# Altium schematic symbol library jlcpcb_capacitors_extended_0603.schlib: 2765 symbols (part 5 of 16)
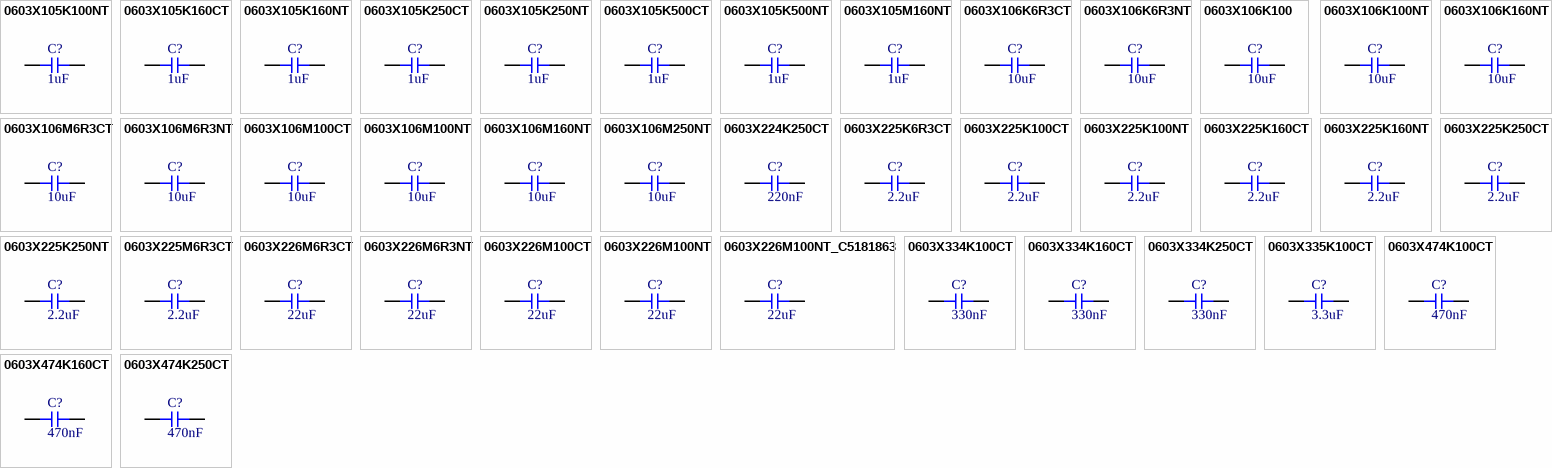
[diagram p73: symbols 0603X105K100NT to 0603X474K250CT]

## 0603X474K250CT
designator C?  Capacitance: 470nF  (hidden comment: *)
Capacitor, Ceramic (MLCC), 470nF, ±10%, 25V, X5R, ±10%, SMD 0603; Manufacturer: Walsin Tech Corp; Manufacturer Part Number: 0603X474K250CT
footprint CAP-0603 (0603 (1608M) Capacitor)
pins: 1, 2

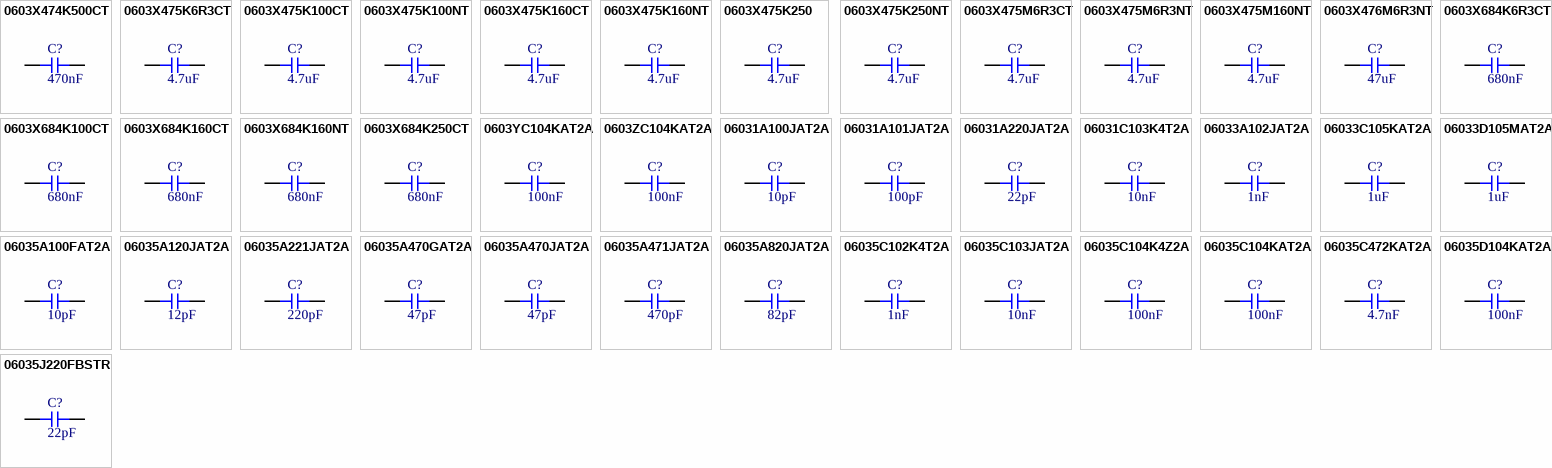
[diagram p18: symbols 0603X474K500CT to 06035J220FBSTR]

## 0603X474K500CT
designator C?  Capacitance: 470nF  (hidden comment: *)
Capacitor, Ceramic (MLCC), 470nF, ±10%, 50V, X5R, ±10%, SMD 0603; Manufacturer: Walsin Tech Corp; Manufacturer Part Number: 0603X474K500CT
footprint CAP-0603 (0603 (1608M) Capacitor)
pins: 1, 2

## 0603X475K6R3CT
designator C?  Capacitance: 4.7uF  (hidden comment: *)
Capacitor, Ceramic (MLCC), 4.7uF, ±10%, 6.3V, X5R, ±10%, SMD 0603; Manufacturer: Walsin Tech Corp; Manufacturer Part Number: 0603X475K6R3CT
footprint CAP-0603 (0603 (1608M) Capacitor)
pins: 1, 2

## 0603X475K100CT
designator C?  Capacitance: 4.7uF  (hidden comment: *)
Capacitor, Ceramic (MLCC), 4.7uF, ±10%, 10V, X5R, ±10%, SMD 0603; Manufacturer: Walsin Tech Corp; Manufacturer Part Number: 0603X475K100CT
footprint CAP-0603 (0603 (1608M) Capacitor)
pins: 1, 2

## 0603X475K100NT
designator C?  Capacitance: 4.7uF  (hidden comment: *)
Capacitor, Ceramic (MLCC), 4.7uF, ±10%, 10V, X5R, ±10%, SMD 0603; Manufacturer: FH(Guangdong Fenghua Advanced Tech); Manufacturer Part Number: 0603X475K100NT
footprint CAP-0603 (0603 (1608M) Capacitor)
pins: 1, 2

## 0603X475K160CT
designator C?  Capacitance: 4.7uF  (hidden comment: *)
Capacitor, Ceramic (MLCC), 4.7uF, ±10%, 16V, X5R, ±10%, SMD 0603; Manufacturer: Walsin Tech Corp; Manufacturer Part Number: 0603X475K160CT
footprint CAP-0603 (0603 (1608M) Capacitor)
pins: 1, 2

## 0603X475K160NT
designator C?  Capacitance: 4.7uF  (hidden comment: *)
Capacitor, Ceramic (MLCC), 4.7uF, ±10%, 16V, X5R, ±10%, SMD 0603; Manufacturer: FH(Guangdong Fenghua Advanced Tech); Manufacturer Part Number: 0603X475K160NT
footprint CAP-0603 (0603 (1608M) Capacitor)
pins: 1, 2

## 0603X475K250
designator C?  Capacitance: 4.7uF  (hidden comment: *)
Capacitor, Ceramic (MLCC), 4.7uF, ±10%, 25V, X5R, ±10%, SMD 0603; Manufacturer: Walsin Tech Corp; Manufacturer Part Number: 0603X475K250
footprint CAP-0603 (0603 (1608M) Capacitor)
pins: 1, 2

## 0603X475K250NT
designator C?  Capacitance: 4.7uF  (hidden comment: *)
Capacitor, Ceramic (MLCC), 4.7uF, ±10%, 25V, X5R, ±10%, SMD 0603; Manufacturer: FH(Guangdong Fenghua Advanced Tech); Manufacturer Part Number: 0603X475K250NT
footprint CAP-0603 (0603 (1608M) Capacitor)
pins: 1, 2

## 0603X475M6R3CT
designator C?  Capacitance: 4.7uF  (hidden comment: *)
Capacitor, Ceramic (MLCC), 4.7uF, ±20%, 6.3V, X5R, ±20%, SMD 0603; Manufacturer: Walsin Tech Corp; Manufacturer Part Number: 0603X475M6R3CT
footprint CAP-0603 (0603 (1608M) Capacitor)
pins: 1, 2

## 0603X475M6R3NT
designator C?  Capacitance: 4.7uF  (hidden comment: *)
Capacitor, Ceramic (MLCC), 4.7uF, ±20%, 6.3V, X5R, ±20%, SMD 0603; Manufacturer: FH(Guangdong Fenghua Advanced Tech); Manufacturer Part Number: 0603X475M6R3NT
footprint CAP-0603 (0603 (1608M) Capacitor)
pins: 1, 2

## 0603X475M160NT
designator C?  Capacitance: 4.7uF  (hidden comment: *)
Capacitor, Ceramic (MLCC), 4.7uF, ±20%, 16V, X5R, ±20%, SMD 0603; Manufacturer: FH(Guangdong Fenghua Advanced Tech); Manufacturer Part Number: 0603X475M160NT
footprint CAP-0603 (0603 (1608M) Capacitor)
pins: 1, 2

## 0603X476M6R3NT
designator C?  Capacitance: 47uF  (hidden comment: *)
Capacitor, Ceramic (MLCC), 47uF, ±20%, 6.3V, X5R, ±20%, SMD 0603; Manufacturer: FH(Guangdong Fenghua Advanced Tech); Manufacturer Part Number: 0603X476M6R3NT
footprint CAP-0603 (0603 (1608M) Capacitor)
pins: 1, 2

## 0603X684K6R3CT
designator C?  Capacitance: 680nF  (hidden comment: *)
Capacitor, Ceramic (MLCC), 680nF, ±10%, 6.3V, X5R, ±10%, SMD 0603; Manufacturer: Walsin Tech Corp; Manufacturer Part Number: 0603X684K6R3CT
footprint CAP-0603 (0603 (1608M) Capacitor)
pins: 1, 2

## 0603X684K100CT
designator C?  Capacitance: 680nF  (hidden comment: *)
Capacitor, Ceramic (MLCC), 680nF, ±10%, 10V, X5R, ±10%, SMD 0603; Manufacturer: Walsin Tech Corp; Manufacturer Part Number: 0603X684K100CT
footprint CAP-0603 (0603 (1608M) Capacitor)
pins: 1, 2

## 0603X684K160CT
designator C?  Capacitance: 680nF  (hidden comment: *)
Capacitor, Ceramic (MLCC), 680nF, ±10%, 16V, X5R, ±10%, SMD 0603; Manufacturer: Walsin Tech Corp; Manufacturer Part Number: 0603X684K160CT
footprint CAP-0603 (0603 (1608M) Capacitor)
pins: 1, 2

## 0603X684K160NT
designator C?  Capacitance: 680nF  (hidden comment: *)
Capacitor, Ceramic (MLCC), 680nF, ±10%, 16V, ±10%, SMD 0603; Manufacturer: FH(Guangdong Fenghua Advanced Tech); Manufacturer Part Number: 0603X684K160NT
footprint CAP-0603 (0603 (1608M) Capacitor)
pins: 1, 2

## 0603X684K250CT
designator C?  Capacitance: 680nF  (hidden comment: *)
Capacitor, Ceramic (MLCC), 680nF, ±10%, 25V, X5R, ±10%, SMD 0603; Manufacturer: Walsin Tech Corp; Manufacturer Part Number: 0603X684K250CT
footprint CAP-0603 (0603 (1608M) Capacitor)
pins: 1, 2

## 0603YC104KAT2A
designator C?  Capacitance: 100nF  (hidden comment: *)
Capacitor, Ceramic (MLCC), 100nF, ±10%, 16V, X7R, ±10%, SMD 0603; Manufacturer: AVX; Manufacturer Part Number: 0603YC104KAT2A
footprint CAP-0603 (0603 (1608M) Capacitor)
pins: 1, 2

## 0603ZC104KAT2A
designator C?  Capacitance: 100nF  (hidden comment: *)
Capacitor, Ceramic (MLCC), 100nF, ±10%, 10V, X7R, ±10%, SMD 0603; Manufacturer: AVX; Manufacturer Part Number: 0603ZC104KAT2A
footprint CAP-0603 (0603 (1608M) Capacitor)
pins: 1, 2

## 06031A100JAT2A
designator C?  Capacitance: 10pF  (hidden comment: *)
Capacitor, Ceramic (MLCC), 10pF, ±5%, 100V, C0G, ±5%, SMD 0603; Manufacturer: AVX; Manufacturer Part Number: 06031A100JAT2A
footprint CAP-0603 (0603 (1608M) Capacitor)
pins: 1, 2

## 06031A101JAT2A
designator C?  Capacitance: 100pF  (hidden comment: *)
Capacitor, Ceramic (MLCC), 100pF, ±5%, 100V, C0G, ±5%, SMD 0603; Manufacturer: AVX; Manufacturer Part Number: 06031A101JAT2A
footprint CAP-0603 (0603 (1608M) Capacitor)
pins: 1, 2

## 06031A220JAT2A
designator C?  Capacitance: 22pF  (hidden comment: *)
Capacitor, Ceramic (MLCC), 22pF, ±5%, 100V, C0G, ±5%, SMD 0603; Manufacturer: AVX; Manufacturer Part Number: 06031A220JAT2A
footprint CAP-0603 (0603 (1608M) Capacitor)
pins: 1, 2

## 06031C103K4T2A
designator C?  Capacitance: 10nF  (hidden comment: *)
Capacitor, Ceramic (MLCC), 10nF, ±10%, 100V, X7R, ±10%, SMD 0603; Manufacturer: AVX; Manufacturer Part Number: 06031C103K4T2A
footprint CAP-0603 (0603 (1608M) Capacitor)
pins: 1, 2

## 06033A102JAT2A
designator C?  Capacitance: 1nF  (hidden comment: *)
Capacitor, Ceramic (MLCC), 1nF, ±5%, 25V, C0G, ±5%, SMD 0603; Manufacturer: AVX; Manufacturer Part Number: 06033A102JAT2A
footprint CAP-0603 (0603 (1608M) Capacitor)
pins: 1, 2

## 06033C105KAT2A
designator C?  Capacitance: 1uF  (hidden comment: *)
Capacitor, Ceramic (MLCC), 1uF, ±10%, 25V, X7R, ±10%, SMD 0603; Manufacturer: AVX; Manufacturer Part Number: 06033C105KAT2A
footprint CAP-0603 (0603 (1608M) Capacitor)
pins: 1, 2

## 06033D105MAT2A
designator C?  Capacitance: 1uF  (hidden comment: *)
Capacitor, Ceramic (MLCC), 1uF, ±20%, 25V, X5R, ±20%, SMD 0603; Manufacturer: AVX; Manufacturer Part Number: 06033D105MAT2A
footprint CAP-0603 (0603 (1608M) Capacitor)
pins: 1, 2

## 06035A100FAT2A
designator C?  Capacitance: 10pF  (hidden comment: *)
Capacitor, Ceramic (MLCC), 10pF, ±1%, 50V, C0G, ±1%, SMD 0603; Manufacturer: AVX; Manufacturer Part Number: 06035A100FAT2A
footprint CAP-0603 (0603 (1608M) Capacitor)
pins: 1, 2

## 06035A120JAT2A
designator C?  Capacitance: 12pF  (hidden comment: *)
Capacitor, Ceramic (MLCC), 12pF, ±5%, 50V, C0G, ±5%, SMD 0603; Manufacturer: AVX; Manufacturer Part Number: 06035A120JAT2A
footprint CAP-0603 (0603 (1608M) Capacitor)
pins: 1, 2

## 06035A221JAT2A
designator C?  Capacitance: 220pF  (hidden comment: *)
Capacitor, Ceramic (MLCC), 220pF, ±5%, 50V, C0G, ±5%, SMD 0603; Manufacturer: AVX; Manufacturer Part Number: 06035A221JAT2A
footprint CAP-0603 (0603 (1608M) Capacitor)
pins: 1, 2

## 06035A470GAT2A
designator C?  Capacitance: 47pF  (hidden comment: *)
Capacitor, Ceramic (MLCC), 47pF, ±2%, 50V, C0G, ±2%, SMD 0603; Manufacturer: AVX; Manufacturer Part Number: 06035A470GAT2A
footprint CAP-0603 (0603 (1608M) Capacitor)
pins: 1, 2

## 06035A470JAT2A
designator C?  Capacitance: 47pF  (hidden comment: *)
Capacitor, Ceramic (MLCC), 47pF, ±5%, 50V, C0G, ±5%, SMD 0603; Manufacturer: AVX; Manufacturer Part Number: 06035A470JAT2A
footprint CAP-0603 (0603 (1608M) Capacitor)
pins: 1, 2

## 06035A471JAT2A
designator C?  Capacitance: 470pF  (hidden comment: *)
Capacitor, Ceramic (MLCC), 470pF, ±5%, 50V, C0G, ±5%, SMD 0603; Manufacturer: AVX; Manufacturer Part Number: 06035A471JAT2A
footprint CAP-0603 (0603 (1608M) Capacitor)
pins: 1, 2

## 06035A820JAT2A
designator C?  Capacitance: 82pF  (hidden comment: *)
Capacitor, Ceramic (MLCC), 82pF, ±5%, 50V, C0G, ±5%, SMD 0603; Manufacturer: AVX; Manufacturer Part Number: 06035A820JAT2A
footprint CAP-0603 (0603 (1608M) Capacitor)
pins: 1, 2

## 06035C102K4T2A
designator C?  Capacitance: 1nF  (hidden comment: *)
Capacitor, Ceramic (MLCC), 1nF, ±10%, 50V, X7R, ±10%, SMD 0603; Manufacturer: AVX; Manufacturer Part Number: 06035C102K4T2A
footprint CAP-0603 (0603 (1608M) Capacitor)
pins: 1, 2

## 06035C103JAT2A
designator C?  Capacitance: 10nF  (hidden comment: *)
Capacitor, Ceramic (MLCC), 10nF, ±5%, 50V, X7R, ±5%, SMD 0603; Manufacturer: AVX; Manufacturer Part Number: 06035C103JAT2A
footprint CAP-0603 (0603 (1608M) Capacitor)
pins: 1, 2

## 06035C104K4Z2A
designator C?  Capacitance: 100nF  (hidden comment: *)
Capacitor, Ceramic (MLCC), 100nF, ±10%, 50V, X7R, ±10%, SMD 0603; Manufacturer: AVX; Manufacturer Part Number: 06035C104K4Z2A
footprint CAP-0603 (0603 (1608M) Capacitor)
pins: 1, 2

## 06035C104KAT2A
designator C?  Capacitance: 100nF  (hidden comment: *)
Capacitor, Ceramic (MLCC), 100nF, ±10%, 50V, X7R, ±10%, SMD 0603; Manufacturer: AVX; Manufacturer Part Number: 06035C104KAT2A
footprint CAP-0603 (0603 (1608M) Capacitor)
pins: 1, 2

## 06035C472KAT2A
designator C?  Capacitance: 4.7nF  (hidden comment: *)
Capacitor, Ceramic (MLCC), 4.7nF, ±10%, 50V, X7R, ±10%, SMD 0603; Manufacturer: AVX; Manufacturer Part Number: 06035C472KAT2A
footprint CAP-0603 (0603 (1608M) Capacitor)
pins: 1, 2

## 06035D104KAT2A
designator C?  Capacitance: 100nF  (hidden comment: *)
Capacitor, Ceramic (MLCC), 100nF, ±10%, 50V, X5R, ±10%, SMD 0603; Manufacturer: AVX; Manufacturer Part Number: 06035D104KAT2A
footprint CAP-0603 (0603 (1608M) Capacitor)
pins: 1, 2

## 06035J220FBSTR
designator C?  Capacitance: 22pF  (hidden comment: *)
Capacitor, Ceramic (MLCC), 22pF, ±1%, 50V, ±1%, SMD 0603; Manufacturer: AVX; Manufacturer Part Number: 06035J220FBSTR
footprint CAP-0603 (0603 (1608M) Capacitor)
pins: 1, 2

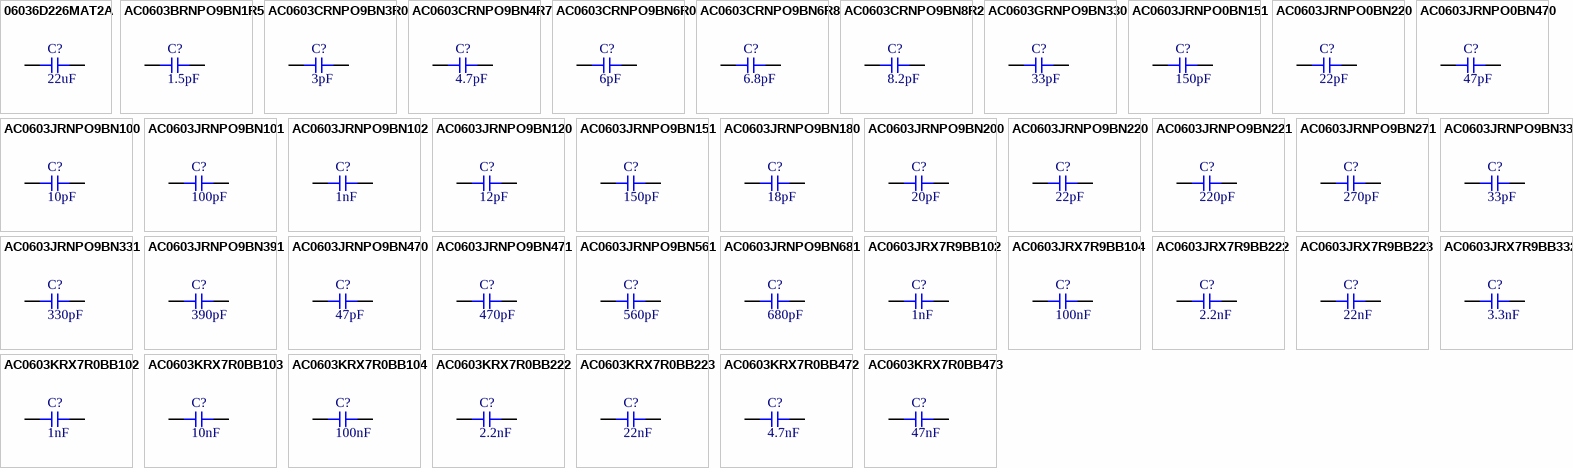
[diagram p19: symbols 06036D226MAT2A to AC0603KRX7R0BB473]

## 06036D226MAT2A
designator C?  Capacitance: 22uF  (hidden comment: *)
Capacitor, Ceramic (MLCC), 22uF, ±20%, 6.3V, X5R, ±20%, SMD 0603; Manufacturer: AVX; Manufacturer Part Number: 06036D226MAT2A
footprint CAP-0603 (0603 (1608M) Capacitor)
pins: 1, 2

## AC0603BRNPO9BN1R5
designator C?  Capacitance: 1.5pF  (hidden comment: *)
Capacitor, Ceramic (MLCC), 1.5pF, ±0.1pF, 50V, NP0, ±0.1pF, SMD 0603; Manufacturer: YAGEO; Manufacturer Part Number: AC0603BRNPO9BN1R5
footprint CAP-0603 (0603 (1608M) Capacitor)
pins: 1, 2

## AC0603CRNPO9BN3R0
designator C?  Capacitance: 3pF  (hidden comment: *)
Capacitor, Ceramic (MLCC), 3pF, ±0.25pF, 50V, NP0, ±0.25pF, SMD 0603; Manufacturer: YAGEO; Manufacturer Part Number: AC0603CRNPO9BN3R0
footprint CAP-0603 (0603 (1608M) Capacitor)
pins: 1, 2

## AC0603CRNPO9BN4R7
designator C?  Capacitance: 4.7pF  (hidden comment: *)
Capacitor, Ceramic (MLCC), 4.7pF, ±0.25pF, 50V, NP0, ±0.25pF, SMD 0603; Manufacturer: YAGEO; Manufacturer Part Number: AC0603CRNPO9BN4R7
footprint CAP-0603 (0603 (1608M) Capacitor)
pins: 1, 2

## AC0603CRNPO9BN6R0
designator C?  Capacitance: 6pF  (hidden comment: *)
Capacitor, Ceramic (MLCC), 6pF, ±0.25pF, 50V, NP0, ±0.25pF, SMD 0603; Manufacturer: YAGEO; Manufacturer Part Number: AC0603CRNPO9BN6R0
footprint CAP-0603 (0603 (1608M) Capacitor)
pins: 1, 2

## AC0603CRNPO9BN6R8
designator C?  Capacitance: 6.8pF  (hidden comment: *)
Capacitor, Ceramic (MLCC), 6.8pF, ±0.25pF, 50V, NP0, ±0.25pF, SMD 0603; Manufacturer: YAGEO; Manufacturer Part Number: AC0603CRNPO9BN6R8
footprint CAP-0603 (0603 (1608M) Capacitor)
pins: 1, 2

## AC0603CRNPO9BN8R2
designator C?  Capacitance: 8.2pF  (hidden comment: *)
Capacitor, Ceramic (MLCC), 8.2pF, ±0.25pF, 50V, NP0, ±0.25pF, SMD 0603; Manufacturer: YAGEO; Manufacturer Part Number: AC0603CRNPO9BN8R2
footprint CAP-0603 (0603 (1608M) Capacitor)
pins: 1, 2

## AC0603GRNPO9BN330
designator C?  Capacitance: 33pF  (hidden comment: *)
Capacitor, Ceramic (MLCC), 33pF, ±2%, 50V, NP0, ±2%, SMD 0603; Manufacturer: YAGEO; Manufacturer Part Number: AC0603GRNPO9BN330
footprint CAP-0603 (0603 (1608M) Capacitor)
pins: 1, 2

## AC0603JRNPO0BN151
designator C?  Capacitance: 150pF  (hidden comment: *)
Capacitor, Ceramic (MLCC), 150pF, ±5%, 100V, NP0, ±5%, SMD 0603; Manufacturer: YAGEO; Manufacturer Part Number: AC0603JRNPO0BN151
footprint CAP-0603 (0603 (1608M) Capacitor)
pins: 1, 2

## AC0603JRNPO0BN220
designator C?  Capacitance: 22pF  (hidden comment: *)
Capacitor, Ceramic (MLCC), 22pF, ±5%, 100V, NP0, ±5%, SMD 0603; Manufacturer: YAGEO; Manufacturer Part Number: AC0603JRNPO0BN220
footprint CAP-0603 (0603 (1608M) Capacitor)
pins: 1, 2

## AC0603JRNPO0BN470
designator C?  Capacitance: 47pF  (hidden comment: *)
Capacitor, Ceramic (MLCC), 47pF, ±5%, 100V, NP0, ±5%, SMD 0603; Manufacturer: YAGEO; Manufacturer Part Number: AC0603JRNPO0BN470
footprint CAP-0603 (0603 (1608M) Capacitor)
pins: 1, 2

## AC0603JRNPO9BN100
designator C?  Capacitance: 10pF  (hidden comment: *)
Capacitor, Ceramic (MLCC), 10pF, ±5%, 50V, NP0, ±5%, SMD 0603; Manufacturer: YAGEO; Manufacturer Part Number: AC0603JRNPO9BN100
footprint CAP-0603 (0603 (1608M) Capacitor)
pins: 1, 2

## AC0603JRNPO9BN101
designator C?  Capacitance: 100pF  (hidden comment: *)
Capacitor, Ceramic (MLCC), 100pF, ±5%, 50V, NP0, ±5%, SMD 0603; Manufacturer: YAGEO; Manufacturer Part Number: AC0603JRNPO9BN101
footprint CAP-0603 (0603 (1608M) Capacitor)
pins: 1, 2

## AC0603JRNPO9BN102
designator C?  Capacitance: 1nF  (hidden comment: *)
Capacitor, Ceramic (MLCC), 1nF, ±5%, 50V, NP0, ±5%, SMD 0603; Manufacturer: YAGEO; Manufacturer Part Number: AC0603JRNPO9BN102
footprint CAP-0603 (0603 (1608M) Capacitor)
pins: 1, 2

## AC0603JRNPO9BN120
designator C?  Capacitance: 12pF  (hidden comment: *)
Capacitor, Ceramic (MLCC), 12pF, ±5%, 50V, NP0, ±5%, SMD 0603; Manufacturer: YAGEO; Manufacturer Part Number: AC0603JRNPO9BN120
footprint CAP-0603 (0603 (1608M) Capacitor)
pins: 1, 2

## AC0603JRNPO9BN151
designator C?  Capacitance: 150pF  (hidden comment: *)
Capacitor, Ceramic (MLCC), 150pF, ±5%, 50V, NP0, ±5%, SMD 0603; Manufacturer: YAGEO; Manufacturer Part Number: AC0603JRNPO9BN151
footprint CAP-0603 (0603 (1608M) Capacitor)
pins: 1, 2

## AC0603JRNPO9BN180
designator C?  Capacitance: 18pF  (hidden comment: *)
Capacitor, Ceramic (MLCC), 18pF, ±5%, 50V, NP0, ±5%, SMD 0603; Manufacturer: YAGEO; Manufacturer Part Number: AC0603JRNPO9BN180
footprint CAP-0603 (0603 (1608M) Capacitor)
pins: 1, 2

## AC0603JRNPO9BN200
designator C?  Capacitance: 20pF  (hidden comment: *)
Capacitor, Ceramic (MLCC), 20pF, ±5%, 50V, NP0, ±5%, SMD 0603; Manufacturer: YAGEO; Manufacturer Part Number: AC0603JRNPO9BN200
footprint CAP-0603 (0603 (1608M) Capacitor)
pins: 1, 2

## AC0603JRNPO9BN220
designator C?  Capacitance: 22pF  (hidden comment: *)
Capacitor, Ceramic (MLCC), 22pF, ±5%, 50V, NP0, ±5%, SMD 0603; Manufacturer: YAGEO; Manufacturer Part Number: AC0603JRNPO9BN220
footprint CAP-0603 (0603 (1608M) Capacitor)
pins: 1, 2

## AC0603JRNPO9BN221
designator C?  Capacitance: 220pF  (hidden comment: *)
Capacitor, Ceramic (MLCC), 220pF, ±5%, 50V, NP0, ±5%, SMD 0603; Manufacturer: YAGEO; Manufacturer Part Number: AC0603JRNPO9BN221
footprint CAP-0603 (0603 (1608M) Capacitor)
pins: 1, 2

## AC0603JRNPO9BN271
designator C?  Capacitance: 270pF  (hidden comment: *)
Capacitor, Ceramic (MLCC), 270pF, ±5%, 50V, NP0, ±5%, SMD 0603; Manufacturer: YAGEO; Manufacturer Part Number: AC0603JRNPO9BN271
footprint CAP-0603 (0603 (1608M) Capacitor)
pins: 1, 2

## AC0603JRNPO9BN330
designator C?  Capacitance: 33pF  (hidden comment: *)
Capacitor, Ceramic (MLCC), 33pF, ±5%, 50V, NP0, ±5%, SMD 0603; Manufacturer: YAGEO; Manufacturer Part Number: AC0603JRNPO9BN330
footprint CAP-0603 (0603 (1608M) Capacitor)
pins: 1, 2

## AC0603JRNPO9BN331
designator C?  Capacitance: 330pF  (hidden comment: *)
Capacitor, Ceramic (MLCC), 330pF, ±5%, 50V, NP0, ±5%, SMD 0603; Manufacturer: YAGEO; Manufacturer Part Number: AC0603JRNPO9BN331
footprint CAP-0603 (0603 (1608M) Capacitor)
pins: 1, 2

## AC0603JRNPO9BN391
designator C?  Capacitance: 390pF  (hidden comment: *)
Capacitor, Ceramic (MLCC), 390pF, ±5%, 50V, NP0, ±5%, SMD 0603; Manufacturer: YAGEO; Manufacturer Part Number: AC0603JRNPO9BN391
footprint CAP-0603 (0603 (1608M) Capacitor)
pins: 1, 2

## AC0603JRNPO9BN470
designator C?  Capacitance: 47pF  (hidden comment: *)
Capacitor, Ceramic (MLCC), 47pF, ±5%, 50V, NP0, ±5%, SMD 0603; Manufacturer: YAGEO; Manufacturer Part Number: AC0603JRNPO9BN470
footprint CAP-0603 (0603 (1608M) Capacitor)
pins: 1, 2

## AC0603JRNPO9BN471
designator C?  Capacitance: 470pF  (hidden comment: *)
Capacitor, Ceramic (MLCC), 470pF, ±5%, 50V, NP0, ±5%, SMD 0603; Manufacturer: YAGEO; Manufacturer Part Number: AC0603JRNPO9BN471
footprint CAP-0603 (0603 (1608M) Capacitor)
pins: 1, 2

## AC0603JRNPO9BN561
designator C?  Capacitance: 560pF  (hidden comment: *)
Capacitor, Ceramic (MLCC), 560pF, ±5%, 50V, NP0, ±5%, SMD 0603; Manufacturer: YAGEO; Manufacturer Part Number: AC0603JRNPO9BN561
footprint CAP-0603 (0603 (1608M) Capacitor)
pins: 1, 2

## AC0603JRNPO9BN681
designator C?  Capacitance: 680pF  (hidden comment: *)
Capacitor, Ceramic (MLCC), 680pF, ±5%, 50V, NP0, ±5%, SMD 0603; Manufacturer: YAGEO; Manufacturer Part Number: AC0603JRNPO9BN681
footprint CAP-0603 (0603 (1608M) Capacitor)
pins: 1, 2

## AC0603JRX7R9BB102
designator C?  Capacitance: 1nF  (hidden comment: *)
Capacitor, Ceramic (MLCC), 1nF, ±5%, 50V, X7R, ±5%, SMD 0603; Manufacturer: YAGEO; Manufacturer Part Number: AC0603JRX7R9BB102
footprint CAP-0603 (0603 (1608M) Capacitor)
pins: 1, 2

## AC0603JRX7R9BB104
designator C?  Capacitance: 100nF  (hidden comment: *)
Capacitor, Ceramic (MLCC), 100nF, ±5%, 50V, X7R, ±5%, SMD 0603; Manufacturer: YAGEO; Manufacturer Part Number: AC0603JRX7R9BB104
footprint CAP-0603 (0603 (1608M) Capacitor)
pins: 1, 2

## AC0603JRX7R9BB222
designator C?  Capacitance: 2.2nF  (hidden comment: *)
Capacitor, Ceramic (MLCC), 2.2nF, ±5%, 50V, X7R, ±5%, SMD 0603; Manufacturer: YAGEO; Manufacturer Part Number: AC0603JRX7R9BB222
footprint CAP-0603 (0603 (1608M) Capacitor)
pins: 1, 2

## AC0603JRX7R9BB223
designator C?  Capacitance: 22nF  (hidden comment: *)
Capacitor, Ceramic (MLCC), 22nF, ±5%, 50V, X7R, ±5%, SMD 0603; Manufacturer: YAGEO; Manufacturer Part Number: AC0603JRX7R9BB223
footprint CAP-0603 (0603 (1608M) Capacitor)
pins: 1, 2

## AC0603JRX7R9BB332
designator C?  Capacitance: 3.3nF  (hidden comment: *)
Capacitor, Ceramic (MLCC), 3.3nF, ±5%, 50V, X7R, ±5%, SMD 0603; Manufacturer: YAGEO; Manufacturer Part Number: AC0603JRX7R9BB332
footprint CAP-0603 (0603 (1608M) Capacitor)
pins: 1, 2

## AC0603KRX7R0BB102
designator C?  Capacitance: 1nF  (hidden comment: *)
Capacitor, Ceramic (MLCC), 1nF, ±10%, 100V, X7R, ±10%, SMD 0603; Manufacturer: YAGEO; Manufacturer Part Number: AC0603KRX7R0BB102
footprint CAP-0603 (0603 (1608M) Capacitor)
pins: 1, 2

## AC0603KRX7R0BB103
designator C?  Capacitance: 10nF  (hidden comment: *)
Capacitor, Ceramic (MLCC), 10nF, ±10%, 100V, X7R, ±10%, SMD 0603; Manufacturer: YAGEO; Manufacturer Part Number: AC0603KRX7R0BB103
footprint CAP-0603 (0603 (1608M) Capacitor)
pins: 1, 2

## AC0603KRX7R0BB104
designator C?  Capacitance: 100nF  (hidden comment: *)
Capacitor, Ceramic (MLCC), 100nF, ±10%, 100V, X7R, ±10%, SMD 0603; Manufacturer: YAGEO; Manufacturer Part Number: AC0603KRX7R0BB104
footprint CAP-0603 (0603 (1608M) Capacitor)
pins: 1, 2

## AC0603KRX7R0BB222
designator C?  Capacitance: 2.2nF  (hidden comment: *)
Capacitor, Ceramic (MLCC), 2.2nF, ±10%, 100V, X7R, ±10%, SMD 0603; Manufacturer: YAGEO; Manufacturer Part Number: AC0603KRX7R0BB222
footprint CAP-0603 (0603 (1608M) Capacitor)
pins: 1, 2

## AC0603KRX7R0BB223
designator C?  Capacitance: 22nF  (hidden comment: *)
Capacitor, Ceramic (MLCC), 22nF, ±10%, 100V, X7R, ±10%, SMD 0603; Manufacturer: YAGEO; Manufacturer Part Number: AC0603KRX7R0BB223
footprint CAP-0603 (0603 (1608M) Capacitor)
pins: 1, 2

## AC0603KRX7R0BB472
designator C?  Capacitance: 4.7nF  (hidden comment: *)
Capacitor, Ceramic (MLCC), 4.7nF, ±10%, 100V, X7R, ±10%, SMD 0603; Manufacturer: YAGEO; Manufacturer Part Number: AC0603KRX7R0BB472
footprint CAP-0603 (0603 (1608M) Capacitor)
pins: 1, 2

## AC0603KRX7R0BB473
designator C?  Capacitance: 47nF  (hidden comment: *)
Capacitor, Ceramic (MLCC), 47nF, ±10%, 100V, X7R, ±10%, SMD 0603; Manufacturer: YAGEO; Manufacturer Part Number: AC0603KRX7R0BB473
footprint CAP-0603 (0603 (1608M) Capacitor)
pins: 1, 2

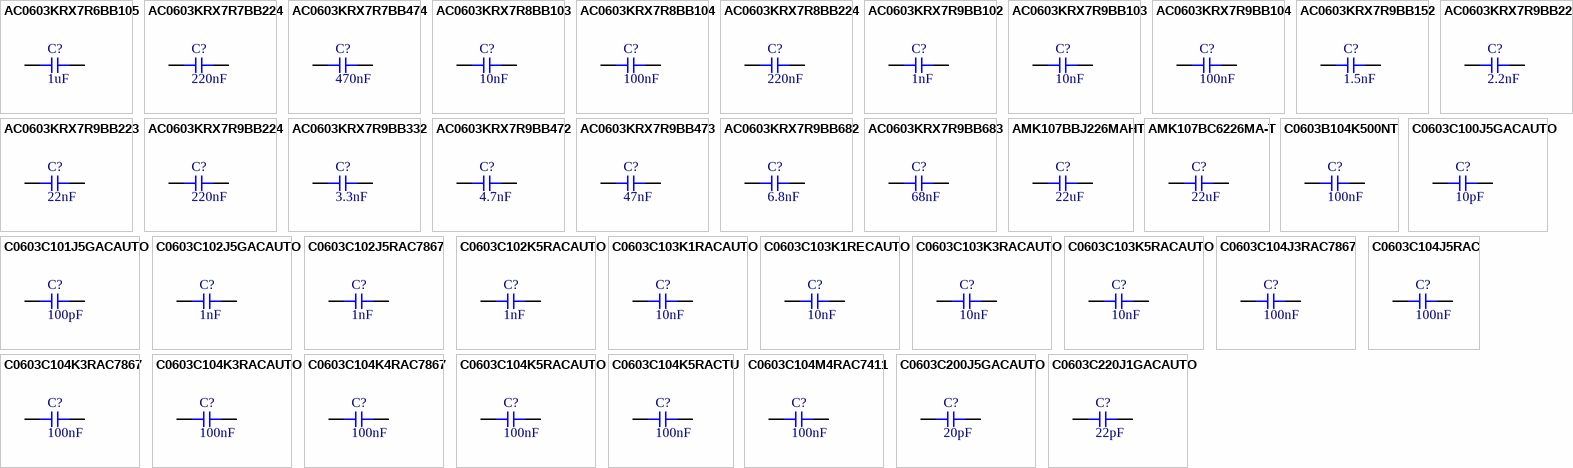
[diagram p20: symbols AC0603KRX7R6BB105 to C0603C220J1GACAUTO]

## AC0603KRX7R6BB105
designator C?  Capacitance: 1uF  (hidden comment: *)
Capacitor, Ceramic (MLCC), 1uF, ±10%, 10V, X7R, ±10%, SMD 0603; Manufacturer: YAGEO; Manufacturer Part Number: AC0603KRX7R6BB105
footprint CAP-0603 (0603 (1608M) Capacitor)
pins: 1, 2

## AC0603KRX7R7BB224
designator C?  Capacitance: 220nF  (hidden comment: *)
Capacitor, Ceramic (MLCC), 220nF, ±10%, 16V, X7R, ±10%, SMD 0603; Manufacturer: YAGEO; Manufacturer Part Number: AC0603KRX7R7BB224
footprint CAP-0603 (0603 (1608M) Capacitor)
pins: 1, 2

## AC0603KRX7R7BB474
designator C?  Capacitance: 470nF  (hidden comment: *)
Capacitor, Ceramic (MLCC), 470nF, ±10%, 16V, X7R, ±10%, SMD 0603; Manufacturer: YAGEO; Manufacturer Part Number: AC0603KRX7R7BB474
footprint CAP-0603 (0603 (1608M) Capacitor)
pins: 1, 2

## AC0603KRX7R8BB103
designator C?  Capacitance: 10nF  (hidden comment: *)
Capacitor, Ceramic (MLCC), 10nF, ±10%, 25V, X7R, ±10%, SMD 0603; Manufacturer: YAGEO; Manufacturer Part Number: AC0603KRX7R8BB103
footprint CAP-0603 (0603 (1608M) Capacitor)
pins: 1, 2

## AC0603KRX7R8BB104
designator C?  Capacitance: 100nF  (hidden comment: *)
Capacitor, Ceramic (MLCC), 100nF, ±10%, 25V, X7R, ±10%, SMD 0603; Manufacturer: YAGEO; Manufacturer Part Number: AC0603KRX7R8BB104
footprint CAP-0603 (0603 (1608M) Capacitor)
pins: 1, 2

## AC0603KRX7R8BB224
designator C?  Capacitance: 220nF  (hidden comment: *)
Capacitor, Ceramic (MLCC), 220nF, ±10%, 25V, X7R, ±10%, SMD 0603; Manufacturer: YAGEO; Manufacturer Part Number: AC0603KRX7R8BB224
footprint CAP-0603 (0603 (1608M) Capacitor)
pins: 1, 2

## AC0603KRX7R9BB102
designator C?  Capacitance: 1nF  (hidden comment: *)
Capacitor, Ceramic (MLCC), 1nF, ±10%, 50V, X7R, ±10%, SMD 0603; Manufacturer: YAGEO; Manufacturer Part Number: AC0603KRX7R9BB102
footprint CAP-0603 (0603 (1608M) Capacitor)
pins: 1, 2

## AC0603KRX7R9BB103
designator C?  Capacitance: 10nF  (hidden comment: *)
Capacitor, Ceramic (MLCC), 10nF, ±10%, 50V, X7R, ±10%, SMD 0603; Manufacturer: YAGEO; Manufacturer Part Number: AC0603KRX7R9BB103
footprint CAP-0603 (0603 (1608M) Capacitor)
pins: 1, 2

## AC0603KRX7R9BB104
designator C?  Capacitance: 100nF  (hidden comment: *)
Capacitor, Ceramic (MLCC), 100nF, ±10%, 50V, X7R, ±10%, SMD 0603; Manufacturer: YAGEO; Manufacturer Part Number: AC0603KRX7R9BB104
footprint CAP-0603 (0603 (1608M) Capacitor)
pins: 1, 2

## AC0603KRX7R9BB152
designator C?  Capacitance: 1.5nF  (hidden comment: *)
Capacitor, Ceramic (MLCC), 1.5nF, ±10%, 50V, X7R, ±10%, SMD 0603; Manufacturer: YAGEO; Manufacturer Part Number: AC0603KRX7R9BB152
footprint CAP-0603 (0603 (1608M) Capacitor)
pins: 1, 2

## AC0603KRX7R9BB222
designator C?  Capacitance: 2.2nF  (hidden comment: *)
Capacitor, Ceramic (MLCC), 2.2nF, ±10%, 50V, X7R, ±10%, SMD 0603; Manufacturer: YAGEO; Manufacturer Part Number: AC0603KRX7R9BB222
footprint CAP-0603 (0603 (1608M) Capacitor)
pins: 1, 2

## AC0603KRX7R9BB223
designator C?  Capacitance: 22nF  (hidden comment: *)
Capacitor, Ceramic (MLCC), 22nF, ±10%, 50V, X7R, ±10%, SMD 0603; Manufacturer: YAGEO; Manufacturer Part Number: AC0603KRX7R9BB223
footprint CAP-0603 (0603 (1608M) Capacitor)
pins: 1, 2

## AC0603KRX7R9BB224
designator C?  Capacitance: 220nF  (hidden comment: *)
Capacitor, Ceramic (MLCC), 220nF, ±10%, 50V, X7R, ±10%, SMD 0603; Manufacturer: YAGEO; Manufacturer Part Number: AC0603KRX7R9BB224
footprint CAP-0603 (0603 (1608M) Capacitor)
pins: 1, 2

## AC0603KRX7R9BB332
designator C?  Capacitance: 3.3nF  (hidden comment: *)
Capacitor, Ceramic (MLCC), 3.3nF, ±10%, 50V, X7R, ±10%, SMD 0603; Manufacturer: YAGEO; Manufacturer Part Number: AC0603KRX7R9BB332
footprint CAP-0603 (0603 (1608M) Capacitor)
pins: 1, 2

## AC0603KRX7R9BB472
designator C?  Capacitance: 4.7nF  (hidden comment: *)
Capacitor, Ceramic (MLCC), 4.7nF, ±10%, 50V, X7R, ±10%, SMD 0603; Manufacturer: YAGEO; Manufacturer Part Number: AC0603KRX7R9BB472
footprint CAP-0603 (0603 (1608M) Capacitor)
pins: 1, 2

## AC0603KRX7R9BB473
designator C?  Capacitance: 47nF  (hidden comment: *)
Capacitor, Ceramic (MLCC), 47nF, ±10%, 50V, X7R, ±10%, SMD 0603; Manufacturer: YAGEO; Manufacturer Part Number: AC0603KRX7R9BB473
footprint CAP-0603 (0603 (1608M) Capacitor)
pins: 1, 2

## AC0603KRX7R9BB682
designator C?  Capacitance: 6.8nF  (hidden comment: *)
Capacitor, Ceramic (MLCC), 6.8nF, ±10%, 50V, X7R, ±10%, SMD 0603; Manufacturer: YAGEO; Manufacturer Part Number: AC0603KRX7R9BB682
footprint CAP-0603 (0603 (1608M) Capacitor)
pins: 1, 2

## AC0603KRX7R9BB683
designator C?  Capacitance: 68nF  (hidden comment: *)
Capacitor, Ceramic (MLCC), 68nF, ±10%, 50V, X7R, ±10%, SMD 0603; Manufacturer: YAGEO; Manufacturer Part Number: AC0603KRX7R9BB683
footprint CAP-0603 (0603 (1608M) Capacitor)
pins: 1, 2

## AMK107BBJ226MAHT
designator C?  Capacitance: 22uF  (hidden comment: *)
Capacitor, Ceramic (MLCC), 22uF, ±20%, 4V, X5R, ±20%, SMD 0603; Manufacturer: Taiyo Yuden; Manufacturer Part Number: AMK107BBJ226MAHT
footprint CAP-0603 (0603 (1608M) Capacitor)
pins: 1, 2

## AMK107BC6226MA-T
designator C?  Capacitance: 22uF  (hidden comment: *)
Capacitor, Ceramic (MLCC), 22uF, ±20%, 4V, X6S, ±20%, SMD 0603; Manufacturer: Taiyo Yuden; Manufacturer Part Number: AMK107BC6226MA-T
footprint CAP-0603 (0603 (1608M) Capacitor)
pins: 1, 2

## C0603B104K500NT
designator C?  Capacitance: 100nF  (hidden comment: *)
Capacitor, Ceramic (MLCC), 100nF, ±10%, 50V, X7R, ±10%, SMD 0603; Manufacturer: TORCH; Manufacturer Part Number: C0603B104K500NT
footprint CAP-0603 (0603 (1608M) Capacitor)
pins: 1, 2

## C0603C100J5GACAUTO
designator C?  Capacitance: 10pF  (hidden comment: *)
Capacitor, Ceramic (MLCC), 10pF, ±5%, 50V, C0G, ±5%, SMD 0603; Manufacturer: KEMET; Manufacturer Part Number: C0603C100J5GACAUTO
footprint CAP-0603 (0603 (1608M) Capacitor)
pins: 1, 2

## C0603C101J5GACAUTO
designator C?  Capacitance: 100pF  (hidden comment: *)
Capacitor, Ceramic (MLCC), 100pF, ±5%, 50V, C0G, ±5%, SMD 0603; Manufacturer: KEMET; Manufacturer Part Number: C0603C101J5GACAUTO
footprint CAP-0603 (0603 (1608M) Capacitor)
pins: 1, 2

## C0603C102J5GACAUTO
designator C?  Capacitance: 1nF  (hidden comment: *)
Capacitor, Ceramic (MLCC), 1nF, ±5%, 50V, C0G, ±5%, SMD 0603; Manufacturer: KEMET; Manufacturer Part Number: C0603C102J5GACAUTO
footprint CAP-0603 (0603 (1608M) Capacitor)
pins: 1, 2

## C0603C102J5RAC7867
designator C?  Capacitance: 1nF  (hidden comment: *)
Capacitor, Ceramic (MLCC), 1nF, ±5%, 50V, X7R, ±5%, SMD 0603; Manufacturer: KEMET; Manufacturer Part Number: C0603C102J5RAC7867
footprint CAP-0603 (0603 (1608M) Capacitor)
pins: 1, 2

## C0603C102K5RACAUTO
designator C?  Capacitance: 1nF  (hidden comment: *)
Capacitor, Ceramic (MLCC), 1nF, ±10%, 50V, X7R, ±10%, SMD 0603; Manufacturer: KEMET; Manufacturer Part Number: C0603C102K5RACAUTO
footprint CAP-0603 (0603 (1608M) Capacitor)
pins: 1, 2

## C0603C103K1RACAUTO
designator C?  Capacitance: 10nF  (hidden comment: *)
Capacitor, Ceramic (MLCC), 10nF, ±10%, 100V, X7R, ±10%, SMD 0603; Manufacturer: KEMET; Manufacturer Part Number: C0603C103K1RACAUTO
footprint CAP-0603 (0603 (1608M) Capacitor)
pins: 1, 2

## C0603C103K1RECAUTO
designator C?  Capacitance: 10nF  (hidden comment: *)
Capacitor, Ceramic (MLCC), 10nF, ±10%, 100V, X7R, ±10%, SMD 0603; Manufacturer: KEMET; Manufacturer Part Number: C0603C103K1RECAUTO
footprint CAP-0603 (0603 (1608M) Capacitor)
pins: 1, 2

## C0603C103K3RACAUTO
designator C?  Capacitance: 10nF  (hidden comment: *)
Capacitor, Ceramic (MLCC), 10nF, ±10%, 25V, X7R, ±10%, SMD 0603; Manufacturer: KEMET; Manufacturer Part Number: C0603C103K3RACAUTO
footprint CAP-0603 (0603 (1608M) Capacitor)
pins: 1, 2

## C0603C103K5RACAUTO
designator C?  Capacitance: 10nF  (hidden comment: *)
Capacitor, Ceramic (MLCC), 10nF, ±10%, 50V, X7R, ±10%, SMD 0603; Manufacturer: KEMET; Manufacturer Part Number: C0603C103K5RACAUTO
footprint CAP-0603 (0603 (1608M) Capacitor)
pins: 1, 2

## C0603C104J3RAC7867
designator C?  Capacitance: 100nF  (hidden comment: *)
Capacitor, Ceramic (MLCC), 100nF, ±5%, 25V, X7R, ±5%, SMD 0603; Manufacturer: KEMET; Manufacturer Part Number: C0603C104J3RAC7867
footprint CAP-0603 (0603 (1608M) Capacitor)
pins: 1, 2

## C0603C104J5RAC
designator C?  Capacitance: 100nF  (hidden comment: *)
Capacitor, Ceramic (MLCC), 100nF, ±5%, 50V, X7R, ±5%, SMD 0603; Manufacturer: KEMET; Manufacturer Part Number: C0603C104J5RAC
footprint CAP-0603 (0603 (1608M) Capacitor)
pins: 1, 2

## C0603C104K3RAC7867
designator C?  Capacitance: 100nF  (hidden comment: *)
Capacitor, Ceramic (MLCC), 100nF, ±10%, 25V, X7R, ±10%, SMD 0603; Manufacturer: KEMET; Manufacturer Part Number: C0603C104K3RAC7867
footprint CAP-0603 (0603 (1608M) Capacitor)
pins: 1, 2

## C0603C104K3RACAUTO
designator C?  Capacitance: 100nF  (hidden comment: *)
Capacitor, Ceramic (MLCC), 100nF, ±10%, 25V, X7R, ±10%, SMD 0603; Manufacturer: KEMET; Manufacturer Part Number: C0603C104K3RACAUTO
footprint CAP-0603 (0603 (1608M) Capacitor)
pins: 1, 2

## C0603C104K4RAC7867
designator C?  Capacitance: 100nF  (hidden comment: *)
Capacitor, Ceramic (MLCC), 100nF, ±10%, 16V, X7R, ±10%, SMD 0603; Manufacturer: KEMET; Manufacturer Part Number: C0603C104K4RAC7867
footprint CAP-0603 (0603 (1608M) Capacitor)
pins: 1, 2

## C0603C104K5RACAUTO
designator C?  Capacitance: 100nF  (hidden comment: *)
Capacitor, Ceramic (MLCC), 100nF, ±10%, 50V, X7R, ±10%, SMD 0603; Manufacturer: KEMET; Manufacturer Part Number: C0603C104K5RACAUTO
footprint CAP-0603 (0603 (1608M) Capacitor)
pins: 1, 2

## C0603C104K5RACTU
designator C?  Capacitance: 100nF  (hidden comment: *)
Capacitor, Ceramic (MLCC), 100nF, ±10%, 50V, X7R, ±10%, SMD 0603; Manufacturer: KEMET; Manufacturer Part Number: C0603C104K5RACTU
footprint CAP-0603 (0603 (1608M) Capacitor)
pins: 1, 2

## C0603C104M4RAC7411
designator C?  Capacitance: 100nF  (hidden comment: *)
Capacitor, Ceramic (MLCC), 100nF, ±20%, 16V, X7R, ±20%, SMD 0603; Manufacturer: KEMET; Manufacturer Part Number: C0603C104M4RAC7411
footprint CAP-0603 (0603 (1608M) Capacitor)
pins: 1, 2

## C0603C200J5GACAUTO
designator C?  Capacitance: 20pF  (hidden comment: *)
Capacitor, Ceramic (MLCC), 20pF, ±5%, 50V, C0G, ±5%, SMD 0603; Manufacturer: KEMET; Manufacturer Part Number: C0603C200J5GACAUTO
footprint CAP-0603 (0603 (1608M) Capacitor)
pins: 1, 2

## C0603C220J1GACAUTO
designator C?  Capacitance: 22pF  (hidden comment: *)
Capacitor, Ceramic (MLCC), 22pF, ±5%, 100V, C0G, ±5%, SMD 0603; Manufacturer: KEMET; Manufacturer Part Number: C0603C220J1GACAUTO
footprint CAP-0603 (0603 (1608M) Capacitor)
pins: 1, 2

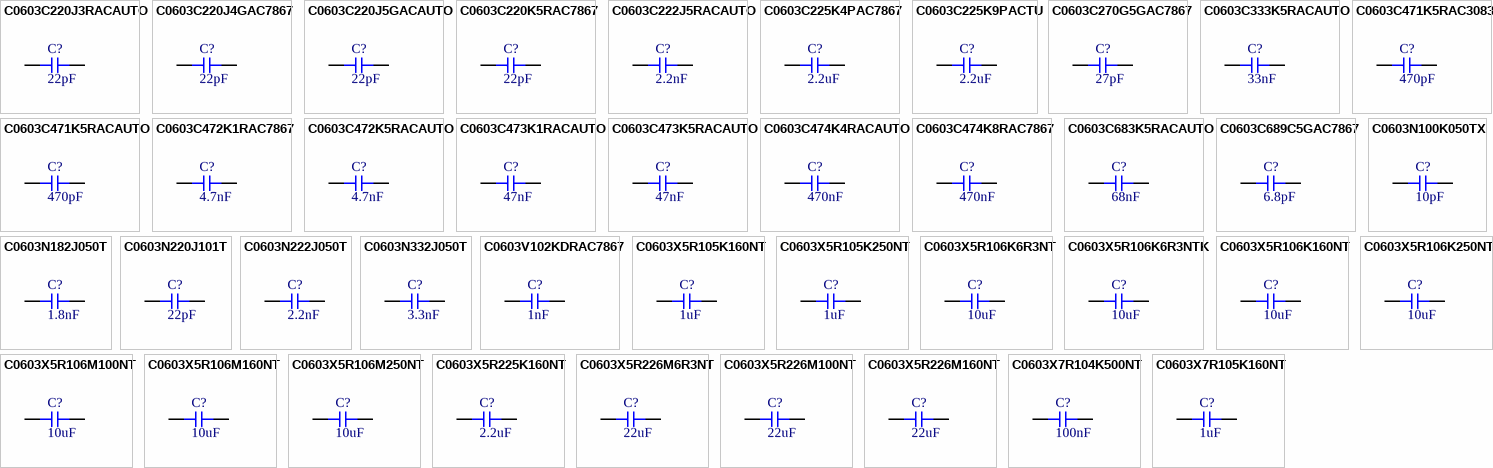
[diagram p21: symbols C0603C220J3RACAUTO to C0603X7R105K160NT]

## C0603C220J3RACAUTO
designator C?  Capacitance: 22pF  (hidden comment: *)
Capacitor, Ceramic (MLCC), 22pF, ±5%, 25V, X7R, ±5%, SMD 0603; Manufacturer: KEMET; Manufacturer Part Number: C0603C220J3RACAUTO
footprint CAP-0603 (0603 (1608M) Capacitor)
pins: 1, 2

## C0603C220J4GAC7867
designator C?  Capacitance: 22pF  (hidden comment: *)
Capacitor, Ceramic (MLCC), 22pF, ±5%, 16V, C0G, ±5%, SMD 0603; Manufacturer: KEMET; Manufacturer Part Number: C0603C220J4GAC7867
footprint CAP-0603 (0603 (1608M) Capacitor)
pins: 1, 2

## C0603C220J5GACAUTO
designator C?  Capacitance: 22pF  (hidden comment: *)
Capacitor, Ceramic (MLCC), 22pF, ±5%, 50V, C0G, ±5%, SMD 0603; Manufacturer: KEMET; Manufacturer Part Number: C0603C220J5GACAUTO
footprint CAP-0603 (0603 (1608M) Capacitor)
pins: 1, 2

## C0603C220K5RAC7867
designator C?  Capacitance: 22pF  (hidden comment: *)
Capacitor, Ceramic (MLCC), 22pF, ±10%, 50V, X7R, ±10%, SMD 0603; Manufacturer: KEMET; Manufacturer Part Number: C0603C220K5RAC7867
footprint CAP-0603 (0603 (1608M) Capacitor)
pins: 1, 2

## C0603C222J5RACAUTO
designator C?  Capacitance: 2.2nF  (hidden comment: *)
Capacitor, Ceramic (MLCC), 2.2nF, ±5%, 50V, X7R, ±5%, SMD 0603; Manufacturer: KEMET; Manufacturer Part Number: C0603C222J5RACAUTO
footprint CAP-0603 (0603 (1608M) Capacitor)
pins: 1, 2

## C0603C225K4PAC7867
designator C?  Capacitance: 2.2uF  (hidden comment: *)
Capacitor, Ceramic (MLCC), 2.2uF, ±10%, 16V, X5R, ±10%, SMD 0603; Manufacturer: KEMET; Manufacturer Part Number: C0603C225K4PAC7867
footprint CAP-0603 (0603 (1608M) Capacitor)
pins: 1, 2

## C0603C225K9PACTU
designator C?  Capacitance: 2.2uF  (hidden comment: *)
Capacitor, Ceramic (MLCC), 2.2uF, ±10%, 6.3V, X5R, ±10%, SMD 0603; Manufacturer: KEMET; Manufacturer Part Number: C0603C225K9PACTU
footprint CAP-0603 (0603 (1608M) Capacitor)
pins: 1, 2

## C0603C270G5GAC7867
designator C?  Capacitance: 27pF  (hidden comment: *)
Capacitor, Ceramic (MLCC), 27pF, ±2%, 50V, C0G, ±2%, SMD 0603; Manufacturer: KEMET; Manufacturer Part Number: C0603C270G5GAC7867
footprint CAP-0603 (0603 (1608M) Capacitor)
pins: 1, 2

## C0603C333K5RACAUTO
designator C?  Capacitance: 33nF  (hidden comment: *)
Capacitor, Ceramic (MLCC), 33nF, ±10%, 50V, X7R, ±10%, SMD 0603; Manufacturer: KEMET; Manufacturer Part Number: C0603C333K5RACAUTO
footprint CAP-0603 (0603 (1608M) Capacitor)
pins: 1, 2

## C0603C471K5RAC3083
designator C?  Capacitance: 470pF  (hidden comment: *)
Capacitor, Ceramic (MLCC), 470pF, ±10%, 50V, X7R, ±10%, SMD 0603; Manufacturer: KEMET; Manufacturer Part Number: C0603C471K5RAC3083
footprint CAP-0603 (0603 (1608M) Capacitor)
pins: 1, 2

## C0603C471K5RACAUTO
designator C?  Capacitance: 470pF  (hidden comment: *)
Capacitor, Ceramic (MLCC), 470pF, ±10%, 50V, X7R, ±10%, SMD 0603; Manufacturer: KEMET; Manufacturer Part Number: C0603C471K5RACAUTO
footprint CAP-0603 (0603 (1608M) Capacitor)
pins: 1, 2

## C0603C472K1RAC7867
designator C?  Capacitance: 4.7nF  (hidden comment: *)
Capacitor, Ceramic (MLCC), 4.7nF, ±10%, 100V, X7R, ±10%, SMD 0603; Manufacturer: KEMET; Manufacturer Part Number: C0603C472K1RAC7867
footprint CAP-0603 (0603 (1608M) Capacitor)
pins: 1, 2

## C0603C472K5RACAUTO
designator C?  Capacitance: 4.7nF  (hidden comment: *)
Capacitor, Ceramic (MLCC), 4.7nF, ±10%, 50V, X7R, ±10%, SMD 0603; Manufacturer: KEMET; Manufacturer Part Number: C0603C472K5RACAUTO
footprint CAP-0603 (0603 (1608M) Capacitor)
pins: 1, 2

## C0603C473K1RACAUTO
designator C?  Capacitance: 47nF  (hidden comment: *)
Capacitor, Ceramic (MLCC), 47nF, ±10%, 100V, X7R, ±10%, SMD 0603; Manufacturer: KEMET; Manufacturer Part Number: C0603C473K1RACAUTO
footprint CAP-0603 (0603 (1608M) Capacitor)
pins: 1, 2

## C0603C473K5RACAUTO
designator C?  Capacitance: 47nF  (hidden comment: *)
Capacitor, Ceramic (MLCC), 47nF, ±10%, 50V, X7R, ±10%, SMD 0603; Manufacturer: KEMET; Manufacturer Part Number: C0603C473K5RACAUTO
footprint CAP-0603 (0603 (1608M) Capacitor)
pins: 1, 2

## C0603C474K4RACAUTO
designator C?  Capacitance: 470nF  (hidden comment: *)
Capacitor, Ceramic (MLCC), 470nF, ±10%, 16V, X7R, ±10%, SMD 0603; Manufacturer: KEMET; Manufacturer Part Number: C0603C474K4RACAUTO
footprint CAP-0603 (0603 (1608M) Capacitor)
pins: 1, 2

## C0603C474K8RAC7867
designator C?  Capacitance: 470nF  (hidden comment: *)
Capacitor, Ceramic (MLCC), 470nF, ±10%, 10V, X7R, ±10%, SMD 0603; Manufacturer: KEMET; Manufacturer Part Number: C0603C474K8RAC7867
footprint CAP-0603 (0603 (1608M) Capacitor)
pins: 1, 2

## C0603C683K5RACAUTO
designator C?  Capacitance: 68nF  (hidden comment: *)
Capacitor, Ceramic (MLCC), 68nF, ±10%, 50V, X7R, ±10%, SMD 0603; Manufacturer: KEMET; Manufacturer Part Number: C0603C683K5RACAUTO
footprint CAP-0603 (0603 (1608M) Capacitor)
pins: 1, 2

## C0603C689C5GAC7867
designator C?  Capacitance: 6.8pF  (hidden comment: *)
Capacitor, Ceramic (MLCC), 6.8pF, ±0.25pF, 50V, C0G, ±0.25pF, SMD 0603; Manufacturer: KEMET; Manufacturer Part Number: C0603C689C5GAC7867
footprint CAP-0603 (0603 (1608M) Capacitor)
pins: 1, 2

## C0603N100K050TX
designator C?  Capacitance: 10pF  (hidden comment: *)
Capacitor, Ceramic (MLCC), 10pF, ±10%, 50V, NP0, ±10%, SMD 0603; Manufacturer: IHHEC(HOLY STONE ENTERPRISE CO., LTD); Manufacturer Part Number: C0603N100K050TX
footprint CAP-0603 (0603 (1608M) Capacitor)
pins: 1, 2

## C0603N182J050T
designator C?  Capacitance: 1.8nF  (hidden comment: *)
Capacitor, Ceramic (MLCC), 1.8nF, ±5%, 50V, NP0, ±5%, SMD 0603; Manufacturer: IHHEC(HOLY STONE ENTERPRISE CO., LTD); Manufacturer Part Number: C0603N182J050T
footprint CAP-0603 (0603 (1608M) Capacitor)
pins: 1, 2

## C0603N220J101T
designator C?  Capacitance: 22pF  (hidden comment: *)
Capacitor, Ceramic (MLCC), 22pF, ±5%, 100V, NP0, ±5%, SMD 0603; Manufacturer: IHHEC(HOLY STONE ENTERPRISE CO., LTD); Manufacturer Part Number: C0603N220J101T
footprint CAP-0603 (0603 (1608M) Capacitor)
pins: 1, 2

## C0603N222J050T
designator C?  Capacitance: 2.2nF  (hidden comment: *)
Capacitor, Ceramic (MLCC), 2.2nF, ±5%, 50V, NP0, ±5%, SMD 0603; Manufacturer: IHHEC(HOLY STONE ENTERPRISE CO., LTD); Manufacturer Part Number: C0603N222J050T
footprint CAP-0603 (0603 (1608M) Capacitor)
pins: 1, 2

## C0603N332J050T
designator C?  Capacitance: 3.3nF  (hidden comment: *)
Capacitor, Ceramic (MLCC), 3.3nF, ±5%, 50V, NP0, ±5%, SMD 0603; Manufacturer: IHHEC(HOLY STONE ENTERPRISE CO., LTD); Manufacturer Part Number: C0603N332J050T
footprint CAP-0603 (0603 (1608M) Capacitor)
pins: 1, 2

## C0603V102KDRAC7867
designator C?  Capacitance: 1nF  (hidden comment: *)
Capacitor, Ceramic (MLCC), 1nF, ±10%, 1kV, X7R, ±10%, SMD 0603; Manufacturer: KEMET; Manufacturer Part Number: C0603V102KDRAC7867
footprint CAP-0603 (0603 (1608M) Capacitor)
pins: 1, 2

## C0603X5R105K160NT
designator C?  Capacitance: 1uF  (hidden comment: *)
Capacitor, Ceramic (MLCC), 1uF, ±10%, 16V, X5R, ±10%, SMD 0603; Manufacturer: SANYEAR; Manufacturer Part Number: C0603X5R105K160NT
footprint CAP-0603 (0603 (1608M) Capacitor)
pins: 1, 2

## C0603X5R105K250NT
designator C?  Capacitance: 1uF  (hidden comment: *)
Capacitor, Ceramic (MLCC), 1uF, ±10%, 25V, X5R, ±10%, SMD 0603; Manufacturer: SANYEAR; Manufacturer Part Number: C0603X5R105K250NT
footprint CAP-0603 (0603 (1608M) Capacitor)
pins: 1, 2

## C0603X5R106K6R3NT
designator C?  Capacitance: 10uF  (hidden comment: *)
Capacitor, Ceramic (MLCC), 10uF, ±10%, 6.3V, X5R, ±10%, SMD 0603; Manufacturer: SANYEAR; Manufacturer Part Number: C0603X5R106K6R3NT
footprint CAP-0603 (0603 (1608M) Capacitor)
pins: 1, 2

## C0603X5R106K6R3NTK
designator C?  Capacitance: 10uF  (hidden comment: *)
Capacitor, Ceramic (MLCC), 10uF, ±10%, 6.3V, X5R, ±10%, SMD 0603; Manufacturer: EYANG(Shenzhen Eyang Tech Development); Manufacturer Part Number: C0603X5R106K6R3NTK
footprint CAP-0603 (0603 (1608M) Capacitor)
pins: 1, 2

## C0603X5R106K160NT
designator C?  Capacitance: 10uF  (hidden comment: *)
Capacitor, Ceramic (MLCC), 10uF, ±10%, 16V, ±10%, SMD 0603; Manufacturer: SANYEAR; Manufacturer Part Number: C0603X5R106K160NT
footprint CAP-0603 (0603 (1608M) Capacitor)
pins: 1, 2

## C0603X5R106K250NT
designator C?  Capacitance: 10uF  (hidden comment: *)
Capacitor, Ceramic (MLCC), 10uF, ±10%, 25V, ±10%, SMD 0603; Manufacturer: SANYEAR; Manufacturer Part Number: C0603X5R106K250NT
footprint CAP-0603 (0603 (1608M) Capacitor)
pins: 1, 2

## C0603X5R106M100NT
designator C?  Capacitance: 10uF  (hidden comment: *)
Capacitor, Ceramic (MLCC), 10uF, ±20%, 10V, X5R, ±20%, SMD 0603; Manufacturer: SANYEAR; Manufacturer Part Number: C0603X5R106M100NT
footprint CAP-0603 (0603 (1608M) Capacitor)
pins: 1, 2

## C0603X5R106M160NT
designator C?  Capacitance: 10uF  (hidden comment: *)
Capacitor, Ceramic (MLCC), 10uF, ±20%, 16V, X5R, ±20%, SMD 0603; Manufacturer: SANYEAR; Manufacturer Part Number: C0603X5R106M160NT
footprint CAP-0603 (0603 (1608M) Capacitor)
pins: 1, 2

## C0603X5R106M250NT
designator C?  Capacitance: 10uF  (hidden comment: *)
Capacitor, Ceramic (MLCC), 10uF, ±20%, 25V, X5R, ±20%, SMD 0603; Manufacturer: SANYEAR; Manufacturer Part Number: C0603X5R106M250NT
footprint CAP-0603 (0603 (1608M) Capacitor)
pins: 1, 2

## C0603X5R225K160NT
designator C?  Capacitance: 2.2uF  (hidden comment: *)
Capacitor, Ceramic (MLCC), 2.2uF, ±10%, 16V, ±10%, SMD 0603; Manufacturer: SANYEAR; Manufacturer Part Number: C0603X5R225K160NT
footprint CAP-0603 (0603 (1608M) Capacitor)
pins: 1, 2

## C0603X5R226M6R3NT
designator C?  Capacitance: 22uF  (hidden comment: *)
Capacitor, Ceramic (MLCC), 22uF, ±20%, 6.3V, X5R, ±20%, SMD 0603; Manufacturer: SANYEAR; Manufacturer Part Number: C0603X5R226M6R3NT
footprint CAP-0603 (0603 (1608M) Capacitor)
pins: 1, 2

## C0603X5R226M100NT
designator C?  Capacitance: 22uF  (hidden comment: *)
Capacitor, Ceramic (MLCC), 22uF, ±20%, 10V, X5R, ±20%, SMD 0603; Manufacturer: SANYEAR; Manufacturer Part Number: C0603X5R226M100NT
footprint CAP-0603 (0603 (1608M) Capacitor)
pins: 1, 2

## C0603X5R226M160NT
designator C?  Capacitance: 22uF  (hidden comment: *)
Capacitor, Ceramic (MLCC), 22uF, ±20%, 16V, ±20%, SMD 0603; Manufacturer: SANYEAR; Manufacturer Part Number: C0603X5R226M160NT
footprint CAP-0603 (0603 (1608M) Capacitor)
pins: 1, 2

## C0603X7R104K500NT
designator C?  Capacitance: 100nF  (hidden comment: *)
Capacitor, Ceramic (MLCC), 100nF, ±10%, 50V, X7R, ±10%, SMD 0603; Manufacturer: SANYEAR; Manufacturer Part Number: C0603X7R104K500NT
footprint CAP-0603 (0603 (1608M) Capacitor)
pins: 1, 2

## C0603X7R105K160NT
designator C?  Capacitance: 1uF  (hidden comment: *)
Capacitor, Ceramic (MLCC), 1uF, ±10%, 16V, X7R, ±10%, SMD 0603; Manufacturer: SANYEAR; Manufacturer Part Number: C0603X7R105K160NT
footprint CAP-0603 (0603 (1608M) Capacitor)
pins: 1, 2

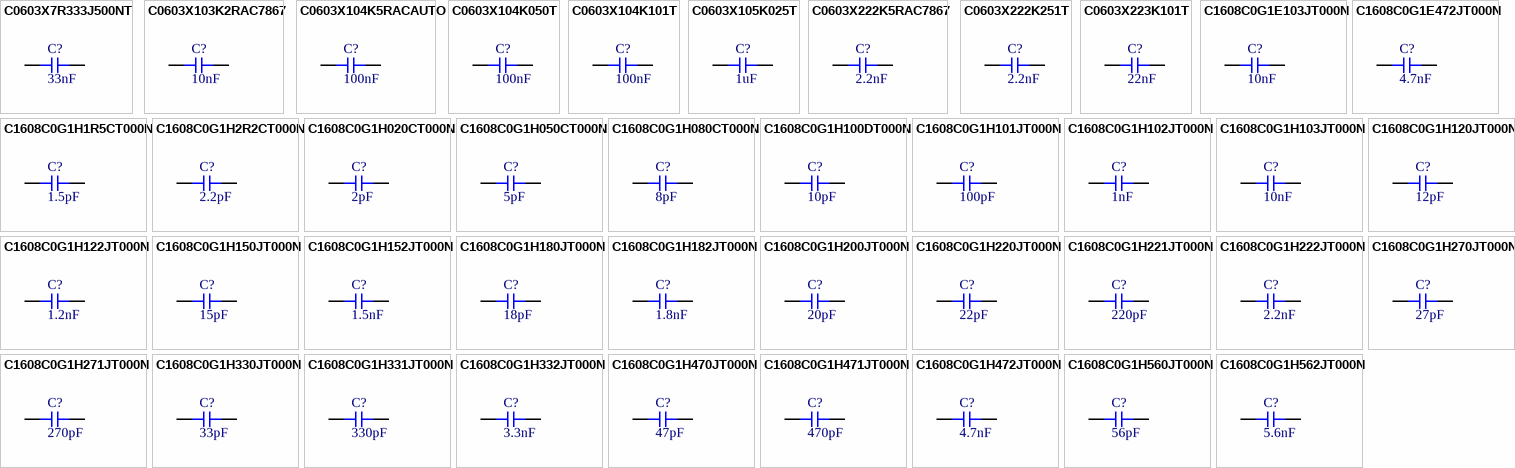
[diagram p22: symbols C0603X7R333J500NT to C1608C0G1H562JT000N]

## C0603X7R333J500NT
designator C?  Capacitance: 33nF  (hidden comment: *)
Capacitor, Ceramic (MLCC), 33nF, ±5%, 50V, ±5%, SMD 0603; Manufacturer: SANYEAR; Manufacturer Part Number: C0603X7R333J500NT
footprint CAP-0603 (0603 (1608M) Capacitor)
pins: 1, 2

## C0603X103K2RAC7867
designator C?  Capacitance: 10nF  (hidden comment: *)
Capacitor, Ceramic (MLCC), 10nF, ±10%, 200V, X7R, ±10%, SMD 0603; Manufacturer: KEMET; Manufacturer Part Number: C0603X103K2RAC7867
footprint CAP-0603 (0603 (1608M) Capacitor)
pins: 1, 2

## C0603X104K5RACAUTO
designator C?  Capacitance: 100nF  (hidden comment: *)
Capacitor, Ceramic (MLCC), 100nF, ±10%, 50V, X7R, ±10%, SMD 0603; Manufacturer: KEMET; Manufacturer Part Number: C0603X104K5RACAUTO
footprint CAP-0603 (0603 (1608M) Capacitor)
pins: 1, 2

## C0603X104K050T
designator C?  Capacitance: 100nF  (hidden comment: *)
Capacitor, Ceramic (MLCC), 100nF, ±10%, 50V, X7R, ±10%, SMD 0603; Manufacturer: IHHEC(HOLY STONE ENTERPRISE CO., LTD); Manufacturer Part Number: C0603X104K050T
footprint CAP-0603 (0603 (1608M) Capacitor)
pins: 1, 2

## C0603X104K101T
designator C?  Capacitance: 100nF  (hidden comment: *)
Capacitor, Ceramic (MLCC), 100nF, ±10%, 100V, X7R, ±10%, SMD 0603; Manufacturer: IHHEC(HOLY STONE ENTERPRISE CO., LTD); Manufacturer Part Number: C0603X104K101T
footprint CAP-0603 (0603 (1608M) Capacitor)
pins: 1, 2

## C0603X105K025T
designator C?  Capacitance: 1uF  (hidden comment: *)
Capacitor, Ceramic (MLCC), 1uF, ±10%, 25V, X7R, ±10%, SMD 0603; Manufacturer: IHHEC(HOLY STONE ENTERPRISE CO., LTD); Manufacturer Part Number: C0603X105K025T
footprint CAP-0603 (0603 (1608M) Capacitor)
pins: 1, 2

## C0603X222K5RAC7867
designator C?  Capacitance: 2.2nF  (hidden comment: *)
Capacitor, Ceramic (MLCC), 2.2nF, ±10%, 50V, X7R, ±10%, SMD 0603; Manufacturer: KEMET; Manufacturer Part Number: C0603X222K5RAC7867
footprint CAP-0603 (0603 (1608M) Capacitor)
pins: 1, 2

## C0603X222K251T
designator C?  Capacitance: 2.2nF  (hidden comment: *)
Capacitor, Ceramic (MLCC), 2.2nF, ±10%, 250V, X7R, ±10%, SMD 0603; Manufacturer: IHHEC(HOLY STONE ENTERPRISE CO., LTD); Manufacturer Part Number: C0603X222K251T
footprint CAP-0603 (0603 (1608M) Capacitor)
pins: 1, 2

## C0603X223K101T
designator C?  Capacitance: 22nF  (hidden comment: *)
Capacitor, Ceramic (MLCC), 22nF, ±10%, 100V, X7R, ±10%, SMD 0603; Manufacturer: IHHEC(HOLY STONE ENTERPRISE CO., LTD); Manufacturer Part Number: C0603X223K101T
footprint CAP-0603 (0603 (1608M) Capacitor)
pins: 1, 2

## C1608C0G1E103JT000N
designator C?  Capacitance: 10nF  (hidden comment: *)
Capacitor, Ceramic (MLCC), 10nF, ±5%, 25V, C0G, ±5%, SMD 0603; Manufacturer: TDK; Manufacturer Part Number: C1608C0G1E103JT000N
footprint CAP-0603 (0603 (1608M) Capacitor)
pins: 1, 2

## C1608C0G1E472JT000N
designator C?  Capacitance: 4.7nF  (hidden comment: *)
Capacitor, Ceramic (MLCC), 4.7nF, ±5%, 25V, C0G, ±5%, SMD 0603; Manufacturer: TDK; Manufacturer Part Number: C1608C0G1E472JT000N
footprint CAP-0603 (0603 (1608M) Capacitor)
pins: 1, 2

## C1608C0G1H1R5CT000N
designator C?  Capacitance: 1.5pF  (hidden comment: *)
Capacitor, Ceramic (MLCC), 1.5pF, ±0.25pF, 50V, C0G, ±0.25pF, SMD 0603; Manufacturer: TDK; Manufacturer Part Number: C1608C0G1H1R5CT000N
footprint CAP-0603 (0603 (1608M) Capacitor)
pins: 1, 2

## C1608C0G1H2R2CT000N
designator C?  Capacitance: 2.2pF  (hidden comment: *)
Capacitor, Ceramic (MLCC), 2.2pF, ±0.25pF, 50V, C0G, ±0.25pF, SMD 0603; Manufacturer: TDK; Manufacturer Part Number: C1608C0G1H2R2CT000N
footprint CAP-0603 (0603 (1608M) Capacitor)
pins: 1, 2

## C1608C0G1H020CT000N
designator C?  Capacitance: 2pF  (hidden comment: *)
Capacitor, Ceramic (MLCC), 2pF, ±0.25pF, 50V, C0G, ±0.25pF, SMD 0603; Manufacturer: TDK; Manufacturer Part Number: C1608C0G1H020CT000N
footprint CAP-0603 (0603 (1608M) Capacitor)
pins: 1, 2

## C1608C0G1H050CT000N
designator C?  Capacitance: 5pF  (hidden comment: *)
Capacitor, Ceramic (MLCC), 5pF, ±0.25pF, 50V, C0G, ±0.25pF, SMD 0603; Manufacturer: TDK; Manufacturer Part Number: C1608C0G1H050CT000N
footprint CAP-0603 (0603 (1608M) Capacitor)
pins: 1, 2

## C1608C0G1H080CT000N
designator C?  Capacitance: 8pF  (hidden comment: *)
Capacitor, Ceramic (MLCC), 8pF, ±0.25pF, 50V, C0G, ±0.25pF, SMD 0603; Manufacturer: TDK; Manufacturer Part Number: C1608C0G1H080CT000N
footprint CAP-0603 (0603 (1608M) Capacitor)
pins: 1, 2

## C1608C0G1H100DT000N
designator C?  Capacitance: 10pF  (hidden comment: *)
Capacitor, Ceramic (MLCC), 10pF, ±0.5pF, 50V, C0G, ±0.5pF, SMD 0603; Manufacturer: TDK; Manufacturer Part Number: C1608C0G1H100DT000N
footprint CAP-0603 (0603 (1608M) Capacitor)
pins: 1, 2

## C1608C0G1H101JT000N
designator C?  Capacitance: 100pF  (hidden comment: *)
Capacitor, Ceramic (MLCC), 100pF, ±5%, 50V, C0G, ±5%, SMD 0603; Manufacturer: TDK; Manufacturer Part Number: C1608C0G1H101JT000N
footprint CAP-0603 (0603 (1608M) Capacitor)
pins: 1, 2

## C1608C0G1H102JT000N
designator C?  Capacitance: 1nF  (hidden comment: *)
Capacitor, Ceramic (MLCC), 1nF, ±5%, 50V, C0G, ±5%, SMD 0603; Manufacturer: TDK; Manufacturer Part Number: C1608C0G1H102JT000N
footprint CAP-0603 (0603 (1608M) Capacitor)
pins: 1, 2

## C1608C0G1H103JT000N
designator C?  Capacitance: 10nF  (hidden comment: *)
Capacitor, Ceramic (MLCC), 10nF, ±5%, 50V, C0G, ±5%, SMD 0603; Manufacturer: TDK; Manufacturer Part Number: C1608C0G1H103JT000N
footprint CAP-0603 (0603 (1608M) Capacitor)
pins: 1, 2

## C1608C0G1H120JT000N
designator C?  Capacitance: 12pF  (hidden comment: *)
Capacitor, Ceramic (MLCC), 12pF, ±5%, 50V, C0G, ±5%, SMD 0603; Manufacturer: TDK; Manufacturer Part Number: C1608C0G1H120JT000N
footprint CAP-0603 (0603 (1608M) Capacitor)
pins: 1, 2

## C1608C0G1H122JT000N
designator C?  Capacitance: 1.2nF  (hidden comment: *)
Capacitor, Ceramic (MLCC), 1.2nF, ±5%, 50V, C0G, ±5%, SMD 0603; Manufacturer: TDK; Manufacturer Part Number: C1608C0G1H122JT000N
footprint CAP-0603 (0603 (1608M) Capacitor)
pins: 1, 2

## C1608C0G1H150JT000N
designator C?  Capacitance: 15pF  (hidden comment: *)
Capacitor, Ceramic (MLCC), 15pF, ±5%, 50V, C0G, ±5%, SMD 0603; Manufacturer: TDK; Manufacturer Part Number: C1608C0G1H150JT000N
footprint CAP-0603 (0603 (1608M) Capacitor)
pins: 1, 2

## C1608C0G1H152JT000N
designator C?  Capacitance: 1.5nF  (hidden comment: *)
Capacitor, Ceramic (MLCC), 1.5nF, ±5%, 50V, C0G, ±5%, SMD 0603; Manufacturer: TDK; Manufacturer Part Number: C1608C0G1H152JT000N
footprint CAP-0603 (0603 (1608M) Capacitor)
pins: 1, 2

## C1608C0G1H180JT000N
designator C?  Capacitance: 18pF  (hidden comment: *)
Capacitor, Ceramic (MLCC), 18pF, ±5%, 50V, C0G, ±5%, SMD 0603; Manufacturer: TDK; Manufacturer Part Number: C1608C0G1H180JT000N
footprint CAP-0603 (0603 (1608M) Capacitor)
pins: 1, 2

## C1608C0G1H182JT000N
designator C?  Capacitance: 1.8nF  (hidden comment: *)
Capacitor, Ceramic (MLCC), 1.8nF, ±5%, 50V, C0G, ±5%, SMD 0603; Manufacturer: TDK; Manufacturer Part Number: C1608C0G1H182JT000N
footprint CAP-0603 (0603 (1608M) Capacitor)
pins: 1, 2

## C1608C0G1H200JT000N
designator C?  Capacitance: 20pF  (hidden comment: *)
Capacitor, Ceramic (MLCC), 20pF, ±5%, 50V, C0G, ±5%, SMD 0603; Manufacturer: TDK; Manufacturer Part Number: C1608C0G1H200JT000N
footprint CAP-0603 (0603 (1608M) Capacitor)
pins: 1, 2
